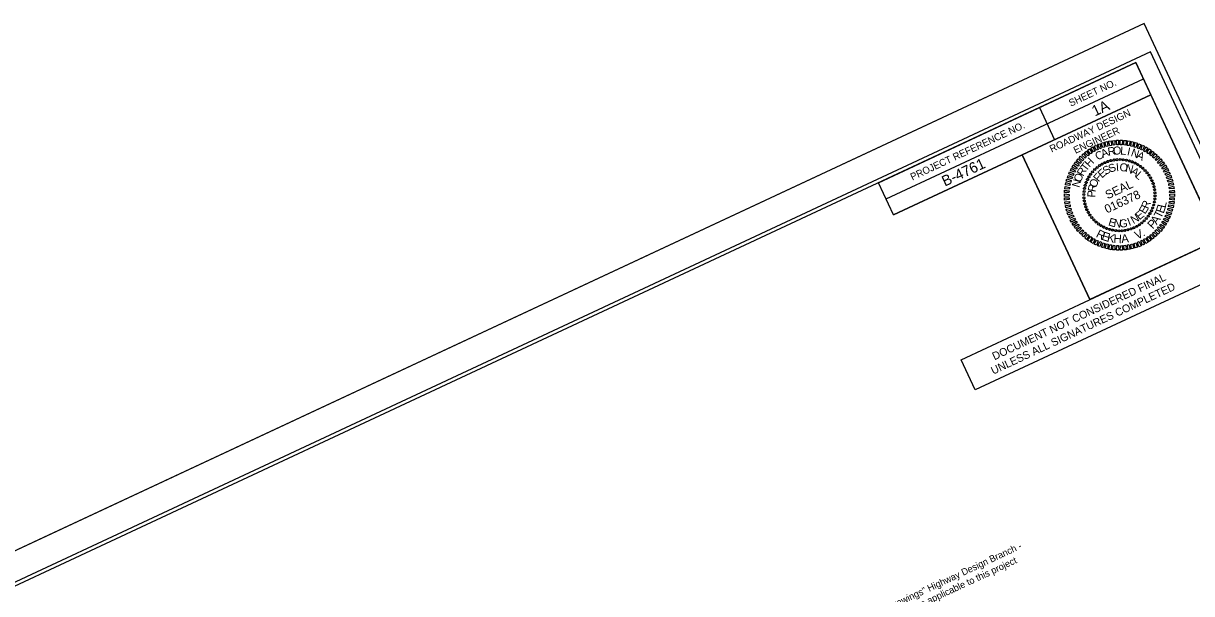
# Model space of a CAD drawing. Extents: x 2321368 to 2323356, y 919896 to 921600.
# Drawn here: x 2322104 to 2322927, y 921198 to 921600 of the extents above; entities that cross this region are included whole.
import ezdxf

# ---------------------------------------------------------------- set-up
doc = ezdxf.new("R2010")
doc.units = 0
for name, color, linetype in [('Default', 7, 'Continuous'), ('Sheet Cutting Line CELL', 7, 'Continuous'), ('Sheet Data Field CELL', 7, 'Continuous'), ('Sheet Plan CELL', 7, 'Continuous'), ('Sheet Plot Border Inside CELL', 7, 'Continuous'), ('Sheet Plot Border Outside CELL', 7, 'Continuous'), ('Sheet Professional Seal CELL', 7, 'Continuous'), ('Sheet Sticker Exception Certification CELL', 7, 'Continuous')]:
    doc.layers.add(name, color=color, linetype=linetype)

msp = doc.modelspace()

# ---------------------------------------------------------------- linework, layer by layer
at = {"layer": 'Sheet Cutting Line CELL'}
msp.add_line((2322893.34, 921599.76), (2321367.8, 920887.79), dxfattribs=at)
at = {"layer": 'Sheet Plan CELL'}
for p, q in [((2322711.48, 921476.21), (2322892.76, 921560.81)), ((2322716.77, 921464.88), (2322898.05, 921549.49)), ((2322716.77, 921464.88), (2322898.05, 921549.49)), ((2322819.51, 921540.42), (2322830.08, 921517.77)), ((2322807.43, 921507.2), (2322854.99, 921405.3))]:
    msp.add_line(p, q, dxfattribs=at)
for points in [[(2322887.45, 921572.19), (2321528.2, 920937.82), (2321972.26, 919986.34), (2323331.51, 920620.71)], [(2322706.17, 921487.58), (2322887.45, 921572.19), (2322898.05, 921549.49), (2322716.77, 921464.88)], [(2322807.43, 921507.2), (2322898.05, 921549.49), (2322945.62, 921447.54), (2322855.01, 921405.25)]]:
    msp.add_lwpolyline(points, close=True, dxfattribs=at)
at = {"layer": 'Sheet Plot Border Inside CELL'}
msp.add_lwpolyline([(2321834.22, 919919.15), (2323343.9, 920623.73), (2322897.72, 921579.74), (2321388.04, 920875.16)], close=True, dxfattribs=at)
at = {"layer": 'Sheet Plot Border Outside CELL'}
msp.add_lwpolyline([(2321830.89, 919895.53), (2323356.43, 920607.51), (2322893.34, 921599.76), (2321367.8, 920887.79)], close=True, dxfattribs=at)
at = {"layer": 'Sheet Professional Seal CELL'}
for p, q in [((2322861.88, 921499.57), (2322861.88, 921499.57)), ((2322863.7, 921500.75), (2322863.7, 921500.75)), ((2322865.67, 921501.73), (2322865.67, 921501.73)), ((2322867.73, 921502.52), (2322867.73, 921502.52)), ((2322869.83, 921503.11), (2322869.83, 921503.11)), ((2322871.92, 921503.59), (2322871.92, 921503.59)), ((2322874.12, 921503.85), (2322874.12, 921503.85)), ((2322876.31, 921503.88), (2322876.31, 921503.88)), ((2322878.5, 921503.79), (2322878.5, 921503.79)), ((2322880.66, 921503.42), (2322880.66, 921503.42)), ((2322882.82, 921502.94), (2322882.82, 921502.94)), ((2322884.86, 921502.24), (2322884.86, 921502.24)), ((2322886.91, 921501.38), (2322886.91, 921501.38)), ((2322888.79, 921500.32), (2322888.79, 921500.32)), ((2322854.35, 921491.7), (2322854.35, 921491.7)), ((2322855.59, 921493.54), (2322855.59, 921493.54)), ((2322856.93, 921495.27), (2322856.93, 921495.27)), ((2322858.41, 921496.84), (2322858.41, 921496.84)), ((2322860.06, 921498.28), (2322860.06, 921498.28)), ((2322890.63, 921499.08), (2322890.63, 921499.08)), ((2322892.36, 921497.74), (2322892.36, 921497.74)), ((2322893.93, 921496.27), (2322893.93, 921496.27)), ((2322895.37, 921494.62), (2322895.37, 921494.62)), ((2322896.66, 921492.79), (2322896.66, 921492.79)), ((2322851.25, 921483.57), (2322851.25, 921483.57)), ((2322851.73, 921485.73), (2322851.73, 921485.73)), ((2322852.43, 921487.77), (2322852.43, 921487.77)), ((2322853.3, 921489.82), (2322853.3, 921489.82)), ((2322897.84, 921490.97), (2322897.84, 921490.97)), ((2322898.82, 921489), (2322898.82, 921489)), ((2322899.61, 921486.94), (2322899.61, 921486.94)), ((2322900.2, 921484.84), (2322900.2, 921484.84)), ((2322850.79, 921479.22), (2322850.79, 921479.22)), ((2322850.82, 921477.03), (2322850.82, 921477.03)), ((2322850.88, 921481.41), (2322850.88, 921481.41)), ((2322851.08, 921474.83), (2322851.08, 921474.83)), ((2322875.88, 921478.79), (2322875.88, 921478.79)), ((2322900.68, 921482.75), (2322900.68, 921482.75)), ((2322900.89, 921476.17), (2322900.89, 921476.17)), ((2322900.94, 921480.55), (2322900.94, 921480.55)), ((2322900.97, 921478.36), (2322900.97, 921478.36)), ((2322851.56, 921472.74), (2322851.56, 921472.74)), ((2322852.15, 921470.64), (2322852.15, 921470.64)), ((2322852.95, 921468.58), (2322852.95, 921468.58)), ((2322853.92, 921466.61), (2322853.92, 921466.61)), ((2322898.47, 921467.76), (2322898.47, 921467.76)), ((2322899.33, 921469.81), (2322899.33, 921469.81)), ((2322900.03, 921471.85), (2322900.03, 921471.85)), ((2322900.51, 921474.01), (2322900.51, 921474.01)), ((2322855.1, 921464.79), (2322855.1, 921464.79)), ((2322856.4, 921462.96), (2322856.4, 921462.96)), ((2322857.83, 921461.32), (2322857.83, 921461.32)), ((2322859.4, 921459.84), (2322859.4, 921459.84)), ((2322861.13, 921458.5), (2322861.13, 921458.5)), ((2322891.71, 921459.3), (2322891.71, 921459.3)), ((2322893.36, 921460.74), (2322893.36, 921460.74)), ((2322894.83, 921462.31), (2322894.83, 921462.31)), ((2322896.17, 921464.04), (2322896.17, 921464.04)), ((2322897.41, 921465.88), (2322897.41, 921465.88)), ((2322862.97, 921457.26), (2322862.97, 921457.26)), ((2322864.85, 921456.2), (2322864.85, 921456.2)), ((2322866.9, 921455.34), (2322866.9, 921455.34)), ((2322868.94, 921454.64), (2322868.94, 921454.64)), ((2322871.1, 921454.16), (2322871.1, 921454.16)), ((2322873.26, 921453.79), (2322873.26, 921453.79)), ((2322875.45, 921453.7), (2322875.45, 921453.7)), ((2322877.64, 921453.73), (2322877.64, 921453.73)), ((2322879.84, 921453.99), (2322879.84, 921453.99)), ((2322881.93, 921454.47), (2322881.93, 921454.47)), ((2322884.03, 921455.06), (2322884.03, 921455.06)), ((2322886.09, 921455.86), (2322886.09, 921455.86)), ((2322888.06, 921456.83), (2322888.06, 921456.83)), ((2322889.88, 921458.01), (2322889.88, 921458.01))]:
    msp.add_line(p, q, dxfattribs=at)
for points in [[(2322864.28, 921512.39), (2322863.09, 921515.42), (2322864.71, 921515.84), (2322865.46, 921512.71)], [(2322866.63, 921513.04), (2322865.68, 921516.13), (2322867.28, 921516.6), (2322867.78, 921513.41)], [(2322869.17, 921513.62), (2322868.25, 921516.78), (2322869.96, 921517.13), (2322870.23, 921513.84)], [(2322871.62, 921514.05), (2322870.99, 921517.17), (2322872.61, 921517.38), (2322872.72, 921514.17)], [(2322874.04, 921514.18), (2322873.75, 921517.52), (2322875.27, 921517.57), (2322875.23, 921514.35)], [(2322876.48, 921514.27), (2322876.37, 921517.48), (2322878.07, 921517.5), (2322877.71, 921514.24)], [(2322879.05, 921514.2), (2322879.07, 921517.36), (2322880.79, 921517.22), (2322880.17, 921514.06)], [(2322881.39, 921513.81), (2322881.75, 921517.17), (2322883.37, 921516.77), (2322882.64, 921513.73)], [(2322883.88, 921513.31), (2322884.39, 921516.59), (2322886.04, 921516.14), (2322885.04, 921513.08)], [(2322886.26, 921512.71), (2322887.02, 921515.94), (2322888.61, 921515.36), (2322887.44, 921512.43)], [(2322851.71, 921504.81), (2322849.4, 921507.04), (2322850.61, 921508.1), (2322852.51, 921505.57)], [(2322853.61, 921506.41), (2322851.33, 921508.82), (2322852.72, 921509.86), (2322854.45, 921507.08)], [(2322855.55, 921507.93), (2322853.47, 921510.49), (2322854.9, 921511.32), (2322856.58, 921508.57)], [(2322857.6, 921509.21), (2322855.75, 921511.88), (2322857.2, 921512.78), (2322858.62, 921509.86)], [(2322859.76, 921510.5), (2322858.16, 921513.34), (2322859.67, 921513.99), (2322860.87, 921510.96)], [(2322861.95, 921511.47), (2322860.58, 921514.41), (2322862.1, 921515.06), (2322863.06, 921511.93)], [(2322888.63, 921511.89), (2322889.58, 921514.93), (2322891.18, 921514.35), (2322889.65, 921511.48)], [(2322890.98, 921511), (2322892.11, 921514.01), (2322893.63, 921513.23), (2322892.03, 921510.39)], [(2322893.16, 921509.86), (2322894.49, 921512.8), (2322895.97, 921511.89), (2322894.11, 921509.26)], [(2322895.21, 921508.56), (2322896.8, 921511.4), (2322898.3, 921510.44), (2322896.26, 921507.95)], [(2322897.31, 921507.11), (2322899.11, 921509.88), (2322900.36, 921508.75), (2322898.26, 921506.51)], [(2322899.13, 921505.59), (2322901.17, 921508.19), (2322902.43, 921507.02), (2322900.05, 921504.8)], [(2322845.37, 921497.11), (2322842.62, 921498.63), (2322843.39, 921500.05), (2322846.12, 921498.12)], [(2322846.84, 921499.17), (2322844.02, 921500.83), (2322845.08, 921502.21), (2322847.44, 921500.11)], [(2322848.28, 921501.17), (2322845.64, 921503.03), (2322846.75, 921504.32), (2322849.08, 921502.04)], [(2322849.83, 921503.05), (2322847.42, 921505.13), (2322848.53, 921506.3), (2322850.83, 921503.85)], [(2322900.94, 921503.84), (2322903.15, 921506.31), (2322904.31, 921505.13), (2322901.84, 921503.1)], [(2322902.68, 921502), (2322905.09, 921504.4), (2322906.06, 921503.03), (2322903.44, 921501.2)], [(2322904.24, 921500.08), (2322906.69, 921502.27), (2322907.68, 921500.86), (2322904.95, 921499.26)], [(2322905.66, 921498.1), (2322908.31, 921500.1), (2322909.16, 921498.63), (2322906.35, 921497.09)], [(2322842.37, 921490.41), (2322839.2, 921491.19), (2322839.84, 921492.76), (2322842.76, 921491.47)], [(2322843.13, 921492.69), (2322840.2, 921493.76), (2322840.78, 921495.35), (2322843.69, 921493.73)], [(2322844.28, 921494.94), (2322841.32, 921496.21), (2322842.1, 921497.73), (2322844.87, 921495.93)], [(2322906.95, 921496.05), (2322909.72, 921497.78), (2322910.53, 921496.29), (2322907.55, 921495)], [(2322908.05, 921493.8), (2322910.93, 921495.31), (2322911.65, 921493.77), (2322908.56, 921492.72)], [(2322909.06, 921491.52), (2322912.05, 921492.8), (2322912.66, 921491.26), (2322909.48, 921490.39)], [(2322840.52, 921483.14), (2322837.35, 921483.32), (2322837.66, 921485.01), (2322840.87, 921484.3)], [(2322841.03, 921485.59), (2322837.87, 921485.99), (2322838.12, 921487.71), (2322841.22, 921486.73)], [(2322841.59, 921487.95), (2322838.41, 921488.62), (2322838.86, 921490.26), (2322841.84, 921489.06)], [(2322909.85, 921489.24), (2322912.88, 921490.32), (2322913.41, 921488.69), (2322910.13, 921488.04)], [(2322910.57, 921486.76), (2322913.54, 921487.71), (2322913.95, 921486.02), (2322910.65, 921485.64)], [(2322910.99, 921484.31), (2322914.08, 921485.03), (2322914.46, 921483.39), (2322911.07, 921483.19)], [(2322840.41, 921478.18), (2322837.11, 921477.91), (2322837.14, 921479.63), (2322840.4, 921479.39)], [(2322840.43, 921475.77), (2322837.24, 921475.27), (2322837.18, 921476.95), (2322840.49, 921476.95)], [(2322840.34, 921480.69), (2322837.23, 921480.62), (2322837.26, 921482.34), (2322840.49, 921481.8)], [(2322911.33, 921481.81), (2322914.52, 921482.31), (2322914.58, 921480.63), (2322911.27, 921480.63)], [(2322911.42, 921476.89), (2322914.53, 921476.96), (2322914.51, 921475.24), (2322911.28, 921475.78)], [(2322911.35, 921479.4), (2322914.65, 921479.67), (2322914.62, 921477.95), (2322911.36, 921478.19)], [(2322840.77, 921473.27), (2322837.69, 921472.55), (2322837.3, 921474.19), (2322840.69, 921474.39)], [(2322841.2, 921470.82), (2322838.22, 921469.88), (2322837.82, 921471.56), (2322841.11, 921471.94)], [(2322841.91, 921468.34), (2322838.88, 921467.26), (2322838.35, 921468.89), (2322841.63, 921469.54)], [(2322842.7, 921466.06), (2322839.71, 921464.78), (2322839.11, 921466.32), (2322842.28, 921467.19)], [(2322909.39, 921467.17), (2322912.57, 921466.39), (2322911.92, 921464.82), (2322909, 921466.11)], [(2322910.17, 921469.63), (2322913.35, 921468.97), (2322912.9, 921467.32), (2322909.92, 921468.52)], [(2322910.73, 921471.99), (2322913.89, 921471.59), (2322913.64, 921469.87), (2322910.54, 921470.85)], [(2322911.24, 921474.44), (2322914.41, 921474.26), (2322914.1, 921472.57), (2322910.9, 921473.28)], [(2322843.71, 921463.78), (2322840.83, 921462.27), (2322840.11, 921463.81), (2322843.2, 921464.86)], [(2322844.81, 921461.53), (2322842.04, 921459.8), (2322841.23, 921461.29), (2322844.22, 921462.58)], [(2322846.1, 921459.48), (2322843.45, 921457.48), (2322842.6, 921458.95), (2322845.41, 921460.49)], [(2322847.52, 921457.5), (2322845.07, 921455.31), (2322844.08, 921456.72), (2322846.81, 921458.32)], [(2322904.92, 921458.41), (2322907.74, 921456.75), (2322906.68, 921455.37), (2322904.32, 921457.47)], [(2322906.39, 921460.47), (2322909.14, 921458.95), (2322908.37, 921457.54), (2322905.65, 921459.47)], [(2322907.48, 921462.64), (2322910.44, 921461.37), (2322909.66, 921459.85), (2322906.89, 921461.65)], [(2322908.63, 921464.89), (2322911.56, 921463.82), (2322910.98, 921462.23), (2322908.07, 921463.85)], [(2322849.08, 921455.58), (2322846.67, 921453.18), (2322845.7, 921454.55), (2322848.32, 921456.38)], [(2322850.82, 921453.74), (2322848.61, 921451.27), (2322847.45, 921452.45), (2322849.93, 921454.48)], [(2322852.63, 921451.99), (2322850.59, 921449.39), (2322849.33, 921450.56), (2322851.71, 921452.78)], [(2322854.45, 921450.47), (2322852.65, 921447.7), (2322851.41, 921448.83), (2322853.5, 921451.08)], [(2322898.15, 921451.17), (2322900.44, 921448.76), (2322899.04, 921447.72), (2322897.31, 921450.5)], [(2322900.05, 921452.77), (2322902.36, 921450.54), (2322901.15, 921449.48), (2322899.25, 921452.01)], [(2322901.93, 921454.53), (2322904.34, 921452.45), (2322903.23, 921451.28), (2322900.93, 921453.73)], [(2322903.48, 921456.41), (2322906.12, 921454.55), (2322905.01, 921453.26), (2322902.68, 921455.54)], [(2322856.56, 921449.02), (2322854.96, 921446.18), (2322853.46, 921447.14), (2322855.5, 921449.63)], [(2322858.6, 921447.72), (2322857.27, 921444.78), (2322855.79, 921445.69), (2322857.66, 921448.32)], [(2322860.78, 921446.58), (2322859.65, 921443.57), (2322858.13, 921444.35), (2322859.73, 921447.19)], [(2322863.13, 921445.69), (2322862.18, 921442.65), (2322860.58, 921443.23), (2322862.11, 921446.1)], [(2322865.5, 921444.87), (2322864.74, 921441.65), (2322863.15, 921442.23), (2322864.32, 921445.15)], [(2322867.88, 921444.27), (2322867.37, 921440.99), (2322865.72, 921441.44), (2322866.72, 921444.5)], [(2322870.37, 921443.78), (2322870.01, 921440.41), (2322868.39, 921440.81), (2322869.12, 921443.85)], [(2322872.71, 921443.38), (2322872.69, 921440.22), (2322870.97, 921440.36), (2322871.6, 921443.52)], [(2322875.28, 921443.31), (2322875.4, 921440.11), (2322873.7, 921440.08), (2322874.05, 921443.34)], [(2322877.72, 921443.4), (2322878.01, 921440.06), (2322876.49, 921440.01), (2322876.53, 921443.23)], [(2322880.14, 921443.53), (2322880.77, 921440.41), (2322879.16, 921440.21), (2322879.04, 921443.41)], [(2322882.59, 921443.96), (2322883.51, 921440.8), (2322881.8, 921440.45), (2322881.53, 921443.74)], [(2322885.13, 921444.54), (2322886.08, 921441.45), (2322884.48, 921440.98), (2322883.98, 921444.17)], [(2322887.48, 921445.19), (2322888.67, 921442.16), (2322887.05, 921441.74), (2322886.31, 921444.87)], [(2322889.81, 921446.11), (2322891.18, 921443.17), (2322889.66, 921442.52), (2322888.7, 921445.65)], [(2322892, 921447.08), (2322893.6, 921444.24), (2322892.09, 921443.59), (2322890.89, 921446.62)], [(2322894.16, 921448.37), (2322896.01, 921445.7), (2322894.56, 921444.8), (2322893.14, 921447.72)], [(2322896.21, 921449.65), (2322898.29, 921447.09), (2322896.86, 921446.26), (2322895.19, 921449.01)]]:
    msp.add_lwpolyline(points, close=True, dxfattribs=at)
for centre, major_axis in [((2322861.85, 921499.58), (-0.403, 0.597)), ((2322863.71, 921500.72), (-0.349, 0.63)), ((2322865.67, 921501.7), (-0.293, 0.658)), ((2322867.71, 921502.5), (-0.235, 0.681)), ((2322869.81, 921503.12), (-0.174, 0.699)), ((2322871.95, 921503.56), (-0.113, 0.711)), ((2322874.12, 921503.81), (-0.05, 0.718)), ((2322876.31, 921503.87), (0.012, 0.72)), ((2322878.49, 921503.73), (0.075, 0.716)), ((2322880.66, 921503.41), (0.137, 0.707)), ((2322882.79, 921502.9), (0.198, 0.692)), ((2322884.86, 921502.21), (0.258, 0.672)), ((2322886.87, 921501.34), (0.315, 0.647)), ((2322888.79, 921500.29), (0.371, 0.617)), ((2322890.62, 921499.09), (0.423, 0.583)), ((2322854.38, 921491.7), (-0.617, 0.371)), ((2322855.59, 921493.53), (-0.583, 0.423)), ((2322856.95, 921495.24), (-0.544, 0.472)), ((2322858.45, 921496.83), (-0.5, 0.518)), ((2322860.09, 921498.28), (-0.453, 0.559)), ((2322892.33, 921497.72), (0.472, 0.544)), ((2322893.92, 921496.22), (0.518, 0.5)), ((2322895.37, 921494.58), (0.559, 0.453)), ((2322896.67, 921492.82), (0.597, 0.403)), ((2322897.81, 921490.96), (0.63, 0.349)), ((2322851.26, 921483.57), (-0.707, 0.137)), ((2322851.77, 921485.7), (-0.692, 0.198)), ((2322852.46, 921487.77), (-0.672, 0.258)), ((2322853.34, 921489.78), (-0.647, 0.315)), ((2322898.79, 921489), (0.658, 0.293)), ((2322899.59, 921486.96), (0.681, 0.235)), ((2322900.21, 921484.87), (0.699, 0.174)), ((2322900.65, 921482.72), (0.711, 0.113)), ((2322850.8, 921479.22), (-0.72, 0.012)), ((2322850.86, 921477.03), (-0.718, -0.05)), ((2322850.94, 921481.4), (-0.716, 0.075)), ((2322851.11, 921474.86), (-0.711, -0.113)), ((2322900.5, 921474.01), (0.707, -0.137)), ((2322900.82, 921476.18), (0.716, -0.075)), ((2322900.9, 921480.55), (0.718, 0.05)), ((2322900.96, 921478.36), (0.72, -0.012)), ((2322851.55, 921472.71), (-0.699, -0.174)), ((2322852.17, 921470.62), (-0.681, -0.235)), ((2322852.97, 921468.58), (-0.658, -0.293)), ((2322853.95, 921466.62), (-0.63, -0.349)), ((2322897.38, 921465.88), (0.617, -0.371)), ((2322898.43, 921467.8), (0.647, -0.315)), ((2322899.3, 921469.81), (0.672, -0.258)), ((2322899.99, 921471.89), (0.692, -0.198)), ((2322855.09, 921464.76), (-0.597, -0.403)), ((2322856.4, 921463), (-0.559, -0.453)), ((2322857.85, 921461.36), (-0.518, -0.5)), ((2322859.43, 921459.86), (-0.472, -0.544)), ((2322861.15, 921458.5), (-0.423, -0.583)), ((2322889.91, 921458), (0.403, -0.597)), ((2322891.67, 921459.3), (0.453, -0.559)), ((2322893.31, 921460.75), (0.5, -0.518)), ((2322894.81, 921462.34), (0.544, -0.472)), ((2322896.18, 921464.06), (0.583, -0.423)), ((2322862.97, 921457.29), (-0.371, -0.617)), ((2322864.89, 921456.24), (-0.315, -0.647)), ((2322866.9, 921455.37), (-0.258, -0.672)), ((2322868.98, 921454.68), (-0.198, -0.692)), ((2322871.1, 921454.17), (-0.137, -0.707)), ((2322873.27, 921453.85), (-0.075, -0.716)), ((2322875.45, 921453.71), (-0.012, -0.72)), ((2322877.64, 921453.77), (0.05, -0.718)), ((2322879.81, 921454.02), (0.113, -0.711)), ((2322881.96, 921454.46), (0.174, -0.699)), ((2322884.05, 921455.08), (0.235, -0.681)), ((2322886.09, 921455.88), (0.293, -0.658)), ((2322888.05, 921456.86), (0.349, -0.63))]:
    msp.add_ellipse(centre, major_axis=major_axis, ratio=0.999708, dxfattribs=at)
at = {"layer": 'Sheet Sticker Exception Certification CELL'}
for p, q in [((2322764.35, 921362.96), (2322945.62, 921447.55)), ((2322955.56, 921426.26), (2322774.29, 921341.66)), ((2322774.29, 921341.66), (2322764.35, 921362.96))]:
    msp.add_line(p, q, dxfattribs=at)

# ---------------------------------------------------------------- texts
at = {"layer": 'Default'}
for s, p in [('The following Roadway Standards as appear in "Roadway Standard Drawings" Highway Design Branch -', (2322537.3, 921104.08)), ('N. C. Department of Transportation - Raleigh, N. C., Dated January, 2012 are applicable to this project', (2322540.59, 921097.01))]:
    msp.add_text(s, height=4.8, rotation=25.01869, dxfattribs=at).set_placement(p)
at = {"layer": 'Sheet Data Field CELL'}
for s, p in [('1A', (2322858.54, 921534.14)), ('B-4761   ', (2322752.86, 921484.76))]:
    msp.add_text(s, height=7.5, rotation=25.01869, dxfattribs=at).set_placement(p)
at = {"layer": 'Sheet Plan CELL'}
for s, height, p in [('SHEET NO.', 5, (2322841.61, 921541.08)), ('ROADWAY DESIGN', 5.0001, (2322828.1, 921508.78)), ('PROJECT REFERENCE NO.', 5.0001, (2322729.97, 921489.09)), ('ENGINEER', 5, (2322844.91, 921507.86))]:
    msp.add_text(s, height=height, rotation=25.01869, dxfattribs=at).set_placement(p)
at = {"layer": 'Sheet Professional Seal CELL'}
for s, height, rotation, p in [('C', 5.64, 31.23856, (2322860.76, 921503.02)), ('A', 5.64, 24.03901, (2322864.22, 921504.96)), ('R', 5.64, 9.63979, (2322868.11, 921506.56)), ('O', 5.64, 2.43986, (2322871.46, 921507.3)), ('L', 5.64, 355.23957, (2322876.23, 921507.48)), ('I', 5.64, 348.03883, (2322880.92, 921507.02)), ('N', 5.64, 340.8376, (2322883.52, 921506.52)), ('A', 5.64, 333.63584, (2322887.44, 921505.1)), ('T', 5.64, 52.83846, (2322852.48, 921495.12)), ('H', 5.64, 45.63817, (2322854.72, 921497.99)), ('S', 5.64, 32.2743, (2322866.22, 921492.88)), ('S', 5.64, 22.91909, (2322869.46, 921494.44)), ('I', 5.64, 4.20829, (2322873.65, 921495.63)), ('O', 5.64, 354.85218, (2322875.76, 921495.84)), ('N', 5.64, 345.4953, (2322879.64, 921495.44)), ('O', 5.64, 67.24043, (2322848.51, 921487.43)), ('R', 5.64, 60.0392, (2322850.33, 921491.69)), ('F', 5.64, 50.98573, (2322861.27, 921487.75)), ('E', 5.64, 41.62976, (2322863.54, 921490.46)), ('A', 5.64, 326.77896, (2322883.32, 921494.29)), ('L', 5.64, 317.41954, (2322886.55, 921491.99)), ('N', 5.64, 74.44219, (2322847.65, 921483.82)), ('R', 5.64, 79.05834, (2322858.98, 921480.72)), ('O', 5.64, 69.69993, (2322859.53, 921483.68)), ('SEAL', 5.998, 25.01869, (2322867.55, 921475.84)), ('P', 5.64, 88.41758, (2322858.88, 921477.15)), ('016378', 5.998, 25.01869, (2322867.1, 921465.85)), ('R', 5.64, 67.5001, (2322896.16, 921468.67)), ('E', 5.64, 39.43045, (2322889.96, 921461.03)), ('E', 5.64, 58.14278, (2322893.94, 921465.04)), ('T', 6, 63.83414, (2322905.16, 921461.95)), ('E', 6, 70.63437, (2322906.95, 921465.54)), ('L', 6, 77.74371, (2322908.35, 921469.49)), ('E', 5.64, 343.29558, (2322867.64, 921457.67)), ('N', 5.64, 352.65265, (2322871.5, 921456.49)), ('G', 5.64, 2.00893, (2322875.89, 921456.06)), ('I', 5.64, 20.71989, (2322882.63, 921457.11)), ('N', 5.64, 30.07508, (2322885.73, 921458.39)), ('P', 6, 47.88449, (2322899.4, 921454.56)), ('A', 6, 54.99383, (2322902.22, 921457.66)), ('R', 6, 333.49917, (2322858.87, 921449.61)), ('E', 6, 340.97943, (2322862.82, 921447.65)), ('K', 6, 348.08877, (2322866.77, 921446.27)), ('H', 6, 356.37269, (2322871.55, 921445.3)), ('A', 6, 6.35668, (2322877.43, 921445.05)), ('V', 6, 25.39734, (2322888.35, 921447.4)), ('.', 6, 33.65036, (2322892.72, 921449.52))]:
    msp.add_text(s, height=height, rotation=rotation, dxfattribs=at).set_placement(p)
at = {"layer": 'Sheet Sticker Exception Certification CELL'}
for s, p in [('DOCUMENT NOT CONSIDERED FINAL', (2322787.82, 921362.49)), ('UNLESS ALL SIGNATURES COMPLETED', (2322786.95, 921352.37))]:
    msp.add_text(s, height=5.5, rotation=25.01869, dxfattribs=at).set_placement(p)

doc.saveas('drawing.dxf')
